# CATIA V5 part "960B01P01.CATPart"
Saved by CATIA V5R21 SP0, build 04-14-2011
Part number: 960B01P01
Bounding box of the stored display mesh (mm): x -33.4 to 33.4, y -150 to 150, z -8 to 13.3
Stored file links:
  C:\Users\ALI OZGUN\Desktop\alhan\960B01P01.CATPart
  C:\Users\ALI OZGUN\Desktop\alhan\943B01P01.CATPart
  C:\Users\ALI OZGUN\Desktop\alhan\950B01P01.CATPart
  C:\Users\ALI OZGUN\Desktop\alhan\Product1.CATProduct
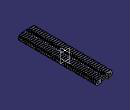
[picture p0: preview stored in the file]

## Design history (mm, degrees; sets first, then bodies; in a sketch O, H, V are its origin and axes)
Set1
  Extract1: ExtractElem face of Pad3 from Sketch4.L4
  Extrapol1: ToExtrapol edge of Extract1, Support Extract1, Length 390
  Symmetry1: Reference yz-plane, ToTransfor Extrapol1
  Split1: ToCut Extrapol1, Cutting Symmetry1
  Trim1: Trimmed (Symmetry1; Split1)
Body1 (main body)
Body2
  Sketch1 on zx-plane, origin (0, 0, 0), H (-1, 0, 0), V (0, 0, 1)
    construction line L1 (25.4, 8) -> (25.4, -8)
    line L2 (25.4, -8) -> (-25.4, -8)
    construction line L3 (-25.4, -8) -> (-25.4, 8)
    line L4 (-25.4, 8) -> (25.4, 8)
    point P3 (-25.4, -8)
    arc A1 centre (25.4, 0) radius 8 from (25.4, 8) to (25.4, -8) cw
    arc A2 centre (-25.4, 0) radius 8 from (-25.4, 8) to (-25.4, -8) ccw
    point P7 (-25.4, -8)
    length L4 = 50.8
    length L3 = 16
    vertical: L1 V, L3 V
    horizontal: L2 H, L4 H
    equidistance: L1 L3 O, L2 L4 O
    tangency: A1 L2, A2 L4, A2 L2, L4 A1
    coincidence: P7 L2, P3 P7
  Pad1: profile Sketch1, direction (0, 1, 0), length 150, mirrored extent
  Sketch2 on zx-plane, origin (0, 0, 0), H (-1, 0, 0), V (0, 0, 1)
    circle A1 centre (25.4, 0) radius 3.15
    circle A2 centre (-25.4, 0) radius 3.15
    radius A1 = 3.15
    radius A2 = 3.15
  Body3
    Sketch3 on face of Pad1 from Sketch1.L4, origin (0, 0, 8), H (1, 0, 0), V (0, 1, 0)
      line L1 (15.5, 146.1) -> (59.5678, 146.1)
      line L2 (59.5678, 146.1) -> (59.5678, 141.5)
      line L3 (59.5678, 141.5) -> (15.5, 141.5)
      line L4 (15.5, 141.5) -> (15.5, 146.1)
      reference projected line E1 (-25.4, 150) -> (25.4, 150) from edge [face of Pad1 from Sketch1.L4 | end face of Pad1]
      distance L1 E1 = 3.9
      distance L4 V = 15.5
      distance L1 L3 = 4.6
      horizontal: L1 H, L3 H
      vertical: L2 V, L4 V
    Pad2: profile Sketch3, direction (0, 0, 1), length 20, mirrored extent
    RectPattern1: of the body so far, direction 1 instances 36, spacing 8.5, along axis of face of Pad1 from Sketch1.A2 reversed
  Remove1: tool Body3
  Body4
    Solid1: linked copy from another document
    Symmetry2: ToTransfor Solid1, Reference yz-plane
    Translate1: Direction zx-plane, ToTransfor Symmetry2, Length 4.25
  Remove2: tool Body4
  Split2: SplitPlane Trim1
  Body5
    Sketch4 on face of Pad1 from Sketch1.L4, origin (0, 0, 8), H (1, 0, 0), V (0, 1, 0)
      projected line E1 (-15.5, 150) -> (25.4, 150) from edge [face of Pad1 from Sketch1.L4 | end face of Pad1]
      projected line E2 (-15.5, 141.85) -> (-25.4, 141.85) from edge [face of Pad1 from Sketch1.L4 | face of Solid1]
      offset line E3 (-15.5, 147.6) -> (25.4, 147.6) from edge [face of Pad1 from Sketch1.L4 | end face of Pad1]
      offset line E4 (-15.5, 144.25) -> (-25.4, 144.25) from edge [face of Pad1 from Sketch1.L4 | face of Solid1]
      line L1 (-7.75, 145.75) -> (-6.1623, 148.5)
      line L2 (10.3499, 146.1) -> (8.7622, 143.35)
      point P9 (33.4, 146.1)
      projected line E6 (-25.4, 145.75) -> (-33.4, 145.75) from edge [face of Solid1 | face of Pad1 from Sketch1.A1]
      point P12 (-33.4, 145.75)
      line L3 (33.4, 146.1) -> (33.4, 148.5)
      line L4 (-33.4, 145.75) -> (-33.4, 143.35)
      projected line E7 (15.5, 146.1) -> (25.4, 146.1) from edge [face of Pad2 from Sketch3.L1 | face of Pad1 from Sketch1.L4]
      projected line E8 (10.3499, 146.1) -> (33.4, 146.1) from edge [face of Pad2 from Sketch3.L1 | face of Pad1 from Sketch1.L4]
      projected line E9 (-15.5, 145.75) -> (-25.4, 145.75) from edge [face of Solid1 | face of Pad1 from Sketch1.L4]
      projected line E10 (-7.75, 145.75) -> (-33.4, 145.75) from edge [face of Solid1 | face of Pad1 from Sketch1.L4]
      offset line E11 (15.5, 148.5) -> (25.4, 148.5) from edge [face of Pad2 from Sketch3.L1 | face of Pad1 from Sketch1.L4]
      offset line E12 (-6.1623, 148.5) -> (33.4, 148.5) from edge [face of Pad2 from Sketch3.L1 | face of Pad1 from Sketch1.L4]
      offset line E13 (-15.5, 143.35) -> (-25.4, 143.35) from edge [face of Solid1 | face of Pad1 from Sketch1.L4]
      offset line E14 (8.7622, 143.35) -> (-33.4, 143.35) from edge [face of Solid1 | face of Pad1 from Sketch1.L4]
      point P25 (-7.75, 145.75)
      angle L1 E1 = 120
      distance E13 E11 = 5.15 (reference)
      distance L1 L2 = 15.5
      distance P25 V = 7.75
      vertical: L3 V, L4 V
      coincidence: P9 L3, P12 L4
    Pad3: profile Sketch4, direction (0, 0, 1), length 5.3, opposite side length 8
    Fillet1: radius 2, on edge [face of Pad3 from Sketch4.E8 | face of Pad3 from Sketch4.L2]; edge [face of Pad3 from Sketch4.L2 | face of Pad3 from Sketch4.E14]; edge [face of Pad3 from Sketch4.L1 | face of Pad3 from Sketch4.E12]; edge [face of Pad3 from Sketch4.E10 | face of Pad3 from Sketch4.L1]
    Draft1: Angle -15, Neutral start face of Pad3, PullDir start face of Pad3, SupportToDraft (face of Pad3 from Sketch4.L4; face of Pad3 from Sketch4.L3)
    Fillet2: radius 4, on edge [face of Pad3 from Sketch4.L3 | end face of Pad3]; edge [face of Pad3 from Sketch4.L4 | end face of Pad3]
    Sketch5 on end face of Pad3, origin (0, 0, 13.3), H (1, 0, 0), V (0, 1, 0)
      point P1 (0, 145.839)
      ellipse A1 centre (0, 145.839) semi-axes 1.2575, 4.4776 rotation 90
      point P2 (0, 147.0965)
      coincidence: P1 V, P2 V, A1 P2
    RectPattern2: of the body so far, direction 1 instances 35, spacing 8.5, along edge [face of Solid1 | face of Pad1 from Sketch1.L4]
  Add1: tool Body5
  Pocket1: profile Sketch2, direction (0, -1, 0), length 204, mirrored extent
  Pocket2: profile Sketch5, direction (0, 0, -1), length 39.3, opposite side length 13
  RectPattern3: of Pocket2, direction 1 instances 35, spacing 8.5, along edge [face of Solid1 | face of Pad1 from Sketch1.L4]
  Sketch6 on face of Pad1 from Sketch1.L2, origin (0, 0, -8), H (1, 0, 0), V (0, -1, 0)
    line L1 (-12.5, -126.5) -> (12.5, -126.5)
    line L2 (12.5, -126.5) -> (12.5, -139.5)
    line L3 (12.5, -139.5) -> (-12.5, -139.5)
    line L4 (-12.5, -139.5) -> (-12.5, -126.5)
    reference projected line E1 (15.5, 134.4) -> (15.5, 139) from edge [face of RectPattern1 | face of Pad1 from Sketch1.L2]
    reference projected line E2 (-15.5, 130.15) -> (-15.5, 134.75) from edge [face of Pad1 from Sketch1.L2 | face of Solid1]
    reference projected line E3 (25.4, -150) -> (-25.4, -150) from edge [face of Pad1 from Sketch1.L2 | end face of Pad1]
    distance L2 E1 = 3
    distance L4 E2 = 3
    length L2 = 13
    distance L3 E3 = 10.5
    horizontal: L1 H, L3 H
    vertical: L2 V, L4 V
  Pocket3: profile Sketch6, direction (0, 0, 1), length 11.3
  RectPattern4: of Pocket3, direction 1 instances 17, spacing 17, along edge [face of RectPattern1 | face of Pad1 from Sketch1.L2]
  RectPattern5: of Pocket3, direction 1 instances 2, spacing 17, along edge [face of RectPattern1 | face of Pad1 from Sketch1.L2] reversed
  RemoveFace1: RemoveFaces (face of RectPattern1; face of Pocket1 from Sketch2.A2; face of Pad1 from Sketch1.A2; face of Split2; face of Pad1 from Sketch1.A2)
Body6
  Solid2: linked copy from another document
  Translate2: Direction yz-plane, ToTransfor Solid2, Length 50.8
Body7
  Solid3: linked copy from another document
  Translate3: Direction yz-plane, ToTransfor Solid3, Length 50.8
Body8
  Solid4: linked copy from another document
  Translate4: Direction yz-plane, Length 50.8, ToTransfor Solid4
  Translate5: Direction zx-plane, ToTransfor Translate4, Length -300
Body9
  Solid5: linked copy from another document
  Translate6: Direction yz-plane, Length 0, ToTransfor Solid5
  Translate7: Direction zx-plane, Length -300, ToTransfor Translate6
